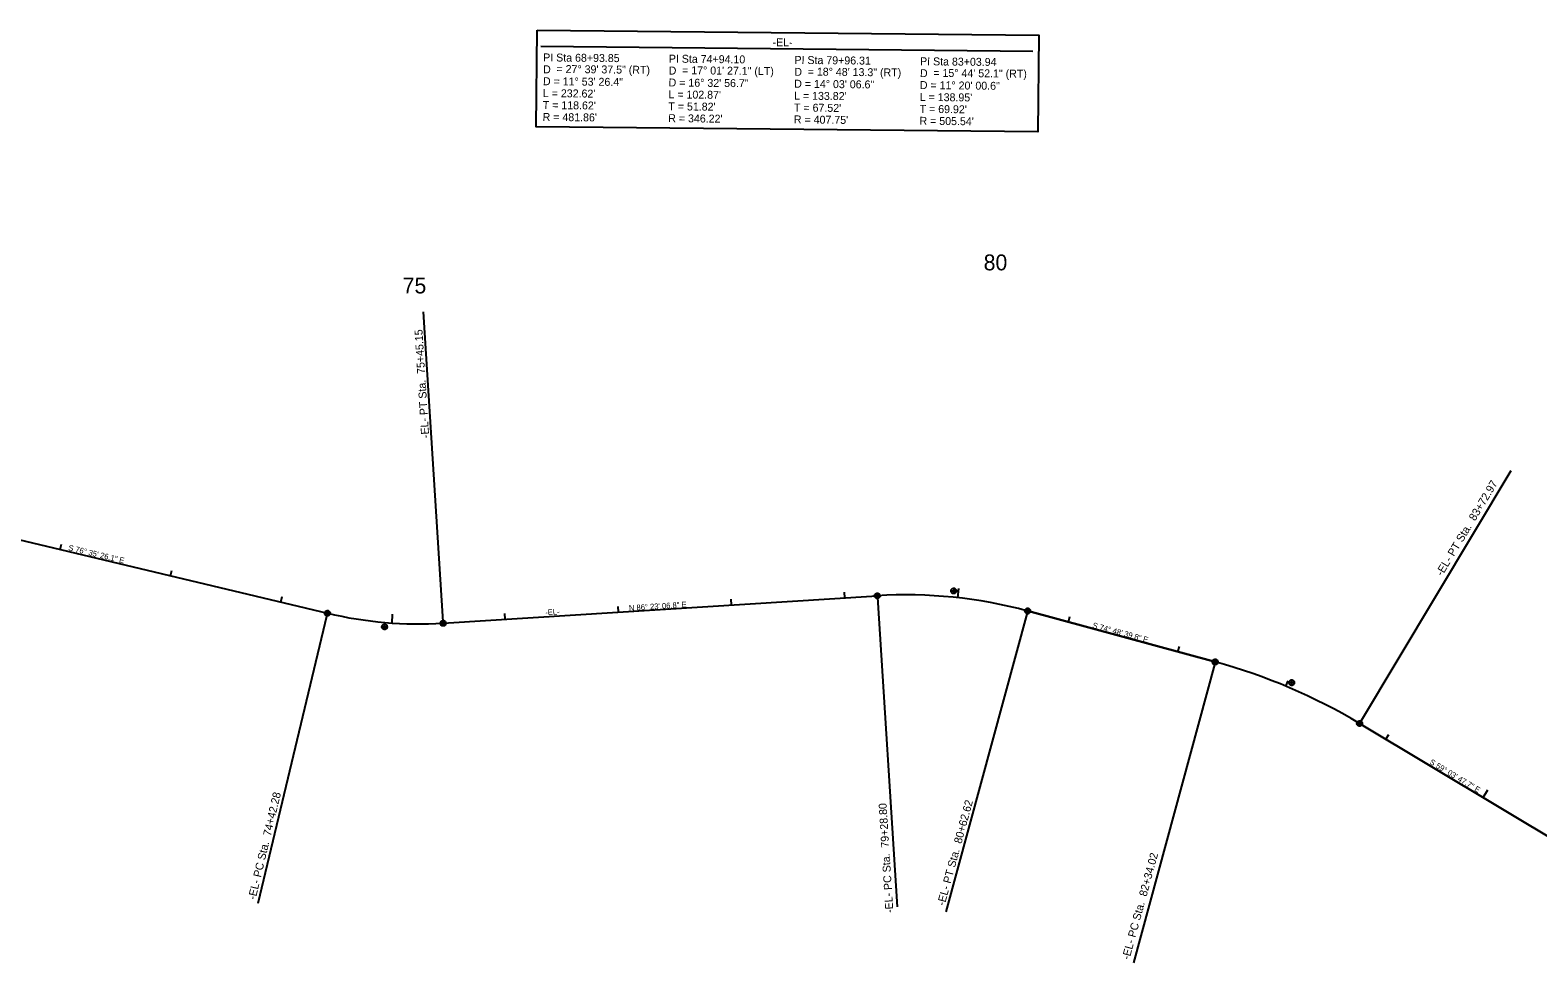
# Model space of a CAD drawing. Extents: x 928071 to 937324, y 684061 to 686812.
# Drawn here: x 933456 to 934785, y 684427 to 685250 of the extents above; entities that cross this region are included whole.
import ezdxf

# ---------------------------------------------------------------- set-up
doc = ezdxf.new("R2010")
doc.units = 0
for name, color, linetype in [('COGO Default Chain', 7, 'Continuous'), ('COGO Default Curve', 7, 'Continuous'), ('Cogo Default Point CELL', 7, 'Continuous'), ('Default', 7, 'Continuous'), ('Exist Horizontal Alignment', 7, 'Continuous'), ('Exist Horizontal Alignment Curve and Spiral Data', 7, 'Continuous'), ('Exist Horizontal Alignment Direction Label', 7, 'Continuous'), ('Exist Horizontal Alignment Station Label', 7, 'Continuous'), ('Exist Horizontal Alignment Tick Label', 7, 'Continuous'), ('Exist Horizontal Alignment Tick Large', 7, 'Continuous'), ('Exist Horizontal Alignment Tick Small', 7, 'Continuous'), ('Prop DSN Text', 7, 'Continuous')]:
    doc.layers.add(name, color=color, linetype=linetype)

msp = doc.modelspace()

# ---------------------------------------------------------------- linework, layer by layer
at = {"layer": 'COGO Default Chain'}
for p, q in [((933295.1, 684836.2), (933717.7, 684735.5)), ((933819.8, 684726.7), (934202.7, 684750.9)), ((934335.3, 684737.5), (934500.7, 684692.6)), ((934628.1, 684638.3), (934812, 684528.1))]:
    msp.add_line(p, q, dxfattribs=at)
for centre, radius, start, end in [((934228.4, 684344), 407.7, 74.8111, 93.6148), ((933798, 685072.3), 346.2, 256.5906, 273.6148), ((934368.2, 684204.7), 505.5, 59.0633, 74.8111)]:
    msp.add_arc(centre, radius, start, end, dxfattribs=at)
at = {"layer": 'COGO Default Curve'}
for centre, radius, start, end in [((934228.4, 684344), 407.7, 74.8111, 93.6148), ((933798, 685072.3), 346.2, 256.5906, 273.6148), ((934368.2, 684204.7), 505.5, 59.0633, 74.8111)]:
    msp.add_arc(centre, radius, start, end, dxfattribs=at)
at = {"layer": 'Cogo Default Point CELL'}
for points in [[(934270.1, 684758.2), (934270.1, 684755.2)], [(934199.7, 684750.9), (934202.7, 684750.9)], [(934202.7, 684753.9), (934202.7, 684750.9)], [(934202.7, 684750.9), (934205.7, 684750.9)], [(934202.7, 684750.9), (934202.7, 684747.9)], [(934267.1, 684755.2), (934270.1, 684755.2)], [(934270.1, 684755.2), (934273.1, 684755.2)], [(934270.1, 684755.2), (934270.1, 684752.2)], [(933714.7, 684735.5), (933717.7, 684735.5)], [(933717.7, 684738.5), (933717.7, 684735.5)], [(933717.7, 684735.5), (933720.7, 684735.5)], [(933717.7, 684735.5), (933717.7, 684732.5)], [(933819.8, 684729.7), (933819.8, 684726.7)], [(934332.3, 684737.5), (934335.3, 684737.5)], [(934335.3, 684740.5), (934335.3, 684737.5)], [(934335.3, 684737.5), (934338.3, 684737.5)], [(934335.3, 684737.5), (934335.3, 684734.5)], [(933765.1, 684723.5), (933768.1, 684723.5)], [(933768.1, 684726.5), (933768.1, 684723.5)], [(933768.1, 684723.5), (933771.1, 684723.5)], [(933768.1, 684723.5), (933768.1, 684720.5)], [(933816.8, 684726.7), (933819.8, 684726.7)], [(933819.8, 684726.7), (933822.8, 684726.7)], [(933819.8, 684726.7), (933819.8, 684723.7)], [(934497.7, 684692.6), (934500.7, 684692.6)], [(934500.7, 684695.6), (934500.7, 684692.6)], [(934500.7, 684692.6), (934503.7, 684692.6)], [(934500.7, 684692.6), (934500.7, 684689.6)], [(934568.1, 684677.3), (934568.1, 684674.3)], [(934565.1, 684674.3), (934568.1, 684674.3)], [(934568.1, 684674.3), (934571.1, 684674.3)], [(934568.1, 684674.3), (934568.1, 684671.3)], [(934625.1, 684638.3), (934628.1, 684638.3)], [(934628.1, 684641.3), (934628.1, 684638.3)], [(934628.1, 684638.3), (934631.1, 684638.3)], [(934628.1, 684638.3), (934628.1, 684635.3)]]:
    msp.add_lwpolyline(points, dxfattribs=at)
for centre in [(934270.1, 684755.2), (934202.7, 684750.9), (933717.7, 684735.5), (934335.3, 684737.5), (933768.1, 684723.5), (933819.8, 684726.7), (934500.7, 684692.6), (934568.1, 684674.3), (934628.1, 684638.3)]:
    msp.add_circle(centre, 2.34, dxfattribs=at)
at = {"layer": 'Default'}
for p, q in [((933295.1, 684836.2), (933717.7, 684735.5)), ((933819.8, 684726.7), (934202.7, 684750.9)), ((934500.7, 684692.6), (934335.3, 684737.5)), ((934812, 684528.1), (934628.1, 684638.3))]:
    msp.add_line(p, q, dxfattribs=at)
msp.add_lwpolyline([(933902.7, 685249.7), (934345.1, 685245.2), (934344.2, 685160), (933901.8, 685164.6)], close=True, dxfattribs=at)
for centre, radius, start, end in [((934228.4, 684344), 407.7, 74.8111, 93.6148), ((933798, 685072.3), 346.2, 256.5906, 273.6148), ((934368.2, 684204.7), 505.5, 59.0633, 74.8111)]:
    msp.add_arc(centre, radius, start, end, dxfattribs=at)
at = {"layer": 'Exist Horizontal Alignment'}
for p, q in [((933295.1, 684836.2), (933717.7, 684735.5)), ((933819.8, 684726.7), (934202.7, 684750.9)), ((934335.3, 684737.5), (934500.7, 684692.6)), ((934628.1, 684638.3), (934812, 684528.1))]:
    msp.add_line(p, q, dxfattribs=at)
for centre, radius, start, end in [((934228.4, 684344), 407.7, 74.8111, 93.6148), ((933798, 685072.3), 346.2, 256.5906, 273.6148), ((934368.2, 684204.7), 505.5, 59.0633, 74.8111)]:
    msp.add_arc(centre, radius, start, end, dxfattribs=at)
at = {"layer": 'Exist Horizontal Alignment Curve and Spiral Data'}
for p in [(933905.8, 685235.6), (934339.9, 685231.2)]:
    msp.add_line(p, (934339.9, 685231.2), dxfattribs=at)
at = {"layer": 'Exist Horizontal Alignment Station Label'}
for p, q in [((933819.7, 684728.2), (933802.5, 685001.2)), ((934761.6, 684861), (934628.9, 684639.6)), ((934202.8, 684749.4), (934220.1, 684476.5)), ((933656.7, 684479.7), (933717.4, 684734)), ((934334.9, 684736), (934263.2, 684472.1)), ((934500.3, 684691.1), (934428.6, 684427.2))]:
    msp.add_line(p, q, dxfattribs=at)
for centre in [(934202.7, 684750.9), (933717.7, 684735.5), (934335.3, 684737.5), (933819.8, 684726.7), (934500.7, 684692.6), (934628.1, 684638.3)]:
    msp.add_circle(centre, 1.5, dxfattribs=at)
at = {"layer": 'Exist Horizontal Alignment Tick Large'}
for p, q in [((934273.8, 684749.2), (934274.7, 684757.2)), ((933774.7, 684726.8), (933775.2, 684734.8)), ((934737.1, 684573), (934741.2, 684579.9))]:
    msp.add_line(p, q, dxfattribs=at)
at = {"layer": 'Exist Horizontal Alignment Tick Small'}
for p, q in [((933482, 684791.7), (933483.2, 684796.5)), ((933579.3, 684768.5), (933580.5, 684773.3)), ((933676.6, 684745.3), (933677.7, 684750.2)), ((934074.2, 684742.8), (934073.9, 684747.8)), ((934174, 684749.1), (934173.7, 684754.1)), ((933874.6, 684730.2), (933874.3, 684735.2)), ((933974.4, 684736.5), (933974.1, 684741.5)), ((934371.3, 684727.7), (934372.6, 684732.5)), ((934467.8, 684701.5), (934469.1, 684706.3)), ((934563, 684671.2), (934565, 684675.8)), ((934651.3, 684624.4), (934653.9, 684628.7))]:
    msp.add_line(p, q, dxfattribs=at)

# ---------------------------------------------------------------- texts
at = {"layer": 'Exist Horizontal Alignment Curve and Spiral Data'}
for s, p in [('-EL-', (934110.3, 685235.6)), ('PI Sta 68+93.85', (933908, 685222.2)), ('PI Sta 74+94.10', (934018.8, 685221.1)), ('PI Sta 79+96.31', (934129.6, 685220)), ('PI Sta 83+03.94', (934240.4, 685218.8)), ('D = 11%%d 53\' 26.4"', (933907.8, 685201.2)), ('D', (933907.9, 685211.7)), ('= 27%%d 39\' 37.5" (RT)', (933919.7, 685212)), ('D', (934018.7, 685210.6)), ('= 17%%d 01\' 27.1" (LT)', (934030.5, 685210.9)), ('D', (934129.5, 685209.5)), ('= 18%%d 48\' 13.3" (RT)', (934141.3, 685209.7)), ('D', (934240.3, 685208.3)), ('= 15%%d 44\' 52.1" (RT)', (934252.1, 685208.6)), ("L = 232.62'", (933907.7, 685190.7)), ("L = 102.87'", (934018.5, 685189.6)), ('D = 16%%d 32\' 56.7"', (934018.6, 685200.1)), ("L = 133.82'", (934129.3, 685188.5)), ('D = 14%%d 03\' 06.6"', (934129.4, 685199)), ('D = 11%%d 20\' 00.6"', (934240.2, 685197.8)), ("T = 118.62'", (933907.6, 685180.2)), ("T = 51.82'", (934018.4, 685179.1)), ("T = 67.52'", (934129.2, 685178)), ("T = 69.92'", (934240, 685176.8)), ("L = 138.95'", (934240.1, 685187.3)), ("R = 481.86'", (933907.5, 685169.7)), ("R = 346.22'", (934018.3, 685168.6)), ("R = 407.75'", (934129.1, 685167.5)), ("R = 505.54'", (934239.9, 685166.3))]:
    msp.add_text(s, height=7, rotation=359.4141, dxfattribs=at).set_placement(p)
at = {"layer": 'Exist Horizontal Alignment Direction Label'}
for s, rotation, p in [('S 76%%d 35\' 26.1" E', 346.5906, (933488.8, 684791.1)), ('N 86%%d 23\' 06.8" E', 3.6148, (933983.8, 684737.6)), ('S 74%%d 48\' 39.8" E', 344.8111, (934392.1, 684722.7)), ('S 59%%d 03\' 47.7" E', 329.0633, (934689.3, 684602.9))]:
    msp.add_text(s, height=5, rotation=rotation, dxfattribs=at).set_placement(p)
at = {"layer": 'Exist Horizontal Alignment Station Label'}
for s, rotation, p in [('-EL- PT Sta.  75+45.15', 93.6148, (933807.5, 684890.2)), ('-EL- PT Sta.  83+72.97', 59.0633, (934700.8, 684767.7)), ('-EL- PC Sta.  74+42.28', 76.5906, (933654.3, 684482.4)), ('-EL- PT Sta.  80+62.62', 74.8111, (934262, 684477.1)), ('-EL- PC Sta.  79+28.80', 93.6148, (934216.9, 684471.4)), ('-EL- PC Sta.  82+34.02', 74.8111, (934425, 684429.5))]:
    msp.add_text(s, height=7, rotation=rotation, dxfattribs=at).set_placement(p)
at = {"layer": 'Exist Horizontal Alignment Tick Label'}
for s, p in [('80', (934296.5, 685037.9)), ('75', (933784.1, 685017.5))]:
    msp.add_text(s, height=14, dxfattribs=at).set_placement(p)
at = {"layer": 'Prop DSN Text'}
msp.add_text('-EL-', height=5, rotation=4.3908, dxfattribs=at).set_placement((933910, 684733.6))

doc.saveas('drawing.dxf')
